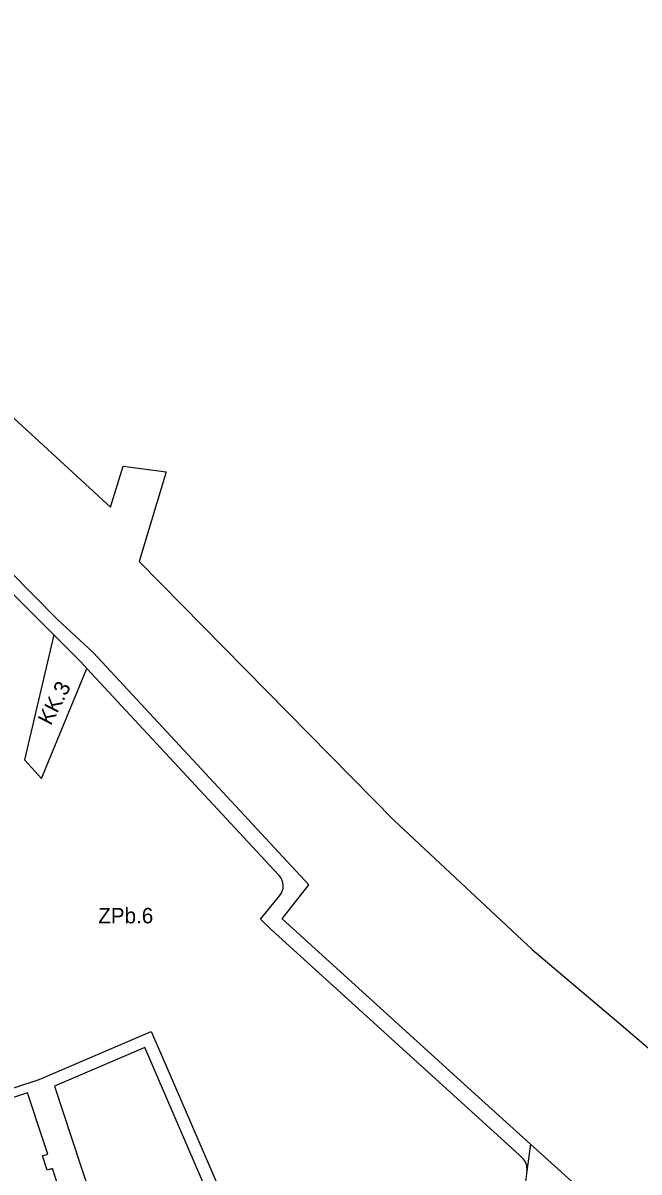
# Model space of a CAD drawing. Extents: x 7416797 to 7419013, y 5549660 to 5551534.
# Drawn here: x 7417678.6 to 7417878.3, y 5550624.8 to 5550997.5 of the extents above; entities that cross this region are included whole.
import ezdxf

# ---------------------------------------------------------------- set-up
doc = ezdxf.new("R2010")
doc.units = 0
for name, color, linetype in [('LIN_Linia Zabudowy Nieprzekraczalna', 7, 'Continuous'), ('LIN_Linia Zabudowy Obowiązujaca', 7, 'Continuous'), ('LIN_linie_rozgraniczajace', 7, 'Continuous'), ('TXT_Oznaczenia_przeznaczen', 7, 'Continuous')]:
    doc.layers.add(name, color=color, linetype=linetype)

msp = doc.modelspace()

# ---------------------------------------------------------------- linework, layer by layer
at = {"layer": 'LIN_Linia Zabudowy Nieprzekraczalna'}
msp.add_lwpolyline([(7417688.86, 5550652.64), (7417709.16, 5550590.9), (7417745.08, 5550602.9), (7417739.25, 5550616.34), (7417718.08, 5550665.17)], close=True, dxfattribs=at)
at = {"layer": 'LIN_Linia Zabudowy Obowiązujaca'}
msp.add_lwpolyline([(7417691.15, 5550616.91), (7417688.17, 5550625.98), (7417686.45, 5550625.42), (7417684.94, 5550630.03), (7417686.66, 5550630.59), (7417685.07, 5550635.43), (7417680.06, 5550650.45), (7417631.75, 5550634.56), (7417633.56, 5550628.97), (7417634.32, 5550629.22), (7417636.01, 5550624.02)], dxfattribs=at)
at = {"layer": 'LIN_linie_rozgraniczajace'}
for points in [[(7417543.24, 5550997.82), (7417547.86, 5550993.46), (7417552.49, 5550989.09), (7417557.03, 5550984.8), (7417565.38, 5550976.91), (7417573.44, 5550969.3), (7417577.11, 5550965.84), (7417581.64, 5550961.56), (7417590.59, 5550953.1), (7417594.55, 5550949.37), (7417598.52, 5550945.61), (7417597.49, 5550942.07), (7417602.31, 5550937.57), (7417651.23, 5550891.75), (7417707.04, 5550840.5), (7417711.06, 5550853.74), (7417725.07, 5550851.88), (7417716.34, 5550822.83), (7417798.86, 5550738.94), (7417843.71, 5550696.94), (7417852.22, 5550689.73), (7417871.75, 5550673.2), (7417881.4, 5550665.03)], [(7417762.67, 5550706.9), (7417771.26, 5550717.97), (7417701.45, 5550793.22), (7417689.8, 5550804.07), (7417627.65, 5550867), (7417602.66, 5550889.86), (7417600.51, 5550891.61), (7417592.25, 5550898.35), (7417577.84, 5550910.26), (7417573.02, 5550914.06), (7417570.5, 5550916.24)], [(7417688.61, 5550799.01), (7417624.22, 5550863.36), (7417600.24, 5550884.74)], [(7417688.61, 5550799.01), (7417679.09, 5550758.5), (7417684.62, 5550752.42), (7417699.35, 5550788.13)], [(7417688.61, 5550799.01), (7417697.49, 5550790.14), (7417699.35, 5550788.13)], [(7417761.65, 5550721), (7417760.09, 5550722.69), (7417699.35, 5550788.13)], [(7417583.18, 5550784.07), (7417636.6, 5550769.97), (7417648.21, 5550734.66), (7417661.07, 5550695.58), (7417675.38, 5550652.06), (7417683.92, 5550654.87), (7417720.17, 5550670.42), (7417723.95, 5550661.71), (7417742.92, 5550617.93), (7417750.48, 5550600.49), (7417755.45, 5550589.02), (7417763, 5550571.61), (7417770.45, 5550574.8), (7417823.65, 5550597.62), (7417839.38, 5550604.37)], [(7417761.84, 5550714.42), (7417762.33, 5550715.12), (7417762.7, 5550715.92), (7417762.93, 5550716.81), (7417762.99, 5550717.75), (7417762.87, 5550718.68), (7417762.59, 5550719.55), (7417762.17, 5550720.34), (7417761.65, 5550721)], [(7417840.44, 5550629.42), (7417839.48, 5550630.43), (7417759.16, 5550703.34), (7417755.6, 5550706.85), (7417760.9, 5550713.27), (7417761.84, 5550714.42)], [(7417822.88, 5550652.23), (7417762.67, 5550706.9)], [(7417843.12, 5550633.86), (7417822.88, 5550652.23)], [(7417843.12, 5550633.86), (7417842.01, 5550625.11)], [(7417843.12, 5550633.86), (7417861.05, 5550617.59), (7417864.45, 5550614.51), (7417861.43, 5550605.65), (7417858.03, 5550595.64), (7417852.21, 5550576.33), (7417853.44, 5550576.05), (7417860.65, 5550574.42), (7417876.38, 5550617.91), (7417876.47, 5550613.94), (7417873.74, 5550605.53)], [(7417842.01, 5550625.11), (7417842.05, 5550625.69), (7417842.02, 5550626.28), (7417841.92, 5550626.87), (7417841.75, 5550627.45), (7417841.51, 5550628.01), (7417841.2, 5550628.53), (7417840.84, 5550629), (7417840.44, 5550629.42)], [(7417842.01, 5550625.11), (7417839.38, 5550604.37)]]:
    msp.add_lwpolyline(points, dxfattribs=at)

# ---------------------------------------------------------------- texts
at = {"layer": 'TXT_Oznaczenia_przeznaczen'}
msp.add_text('KK.3', height=5, rotation=62.7225, dxfattribs=at).set_placement((7417687.65, 5550769.4))
msp.add_text('ZPb.6', height=5, dxfattribs=at).set_placement((7417703.02, 5550705.47))

doc.saveas('drawing.dxf')
